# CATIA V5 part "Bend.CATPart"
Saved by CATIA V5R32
Part number: Bend
Bounding box of the stored display mesh (mm): x -50 to 50, y -150 to 15, z -50 to 115
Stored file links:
  D:\PROJECTS\Project 2022\CATIA V5 6R 2022\Resources\Part Files\c12_catia_v5_6r2022_prt\c12_catia_v5-6r2022 figr_12-44\Bend.CATPart
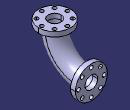
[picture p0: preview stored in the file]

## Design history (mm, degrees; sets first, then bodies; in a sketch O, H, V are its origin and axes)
Body1 (main body)
  Sketch1 on yz-plane, origin (0, 0, 0), H (0, 1, 0), V (0, 0, 1)
    arc A1 centre (0, 100) radius 100 from (-100, 100) to (0, 0) ccw
    point P1 (0, 100)
    coincidence: P1 V
  Sketch2 on zx-plane, origin (0, 0, 0), H (-1, 0, 0), V (0, 0, 1)
    circle A1 centre (0, 0) radius 30
    point P1 (0, -30)
    radius A1 = 30
    coincidence: A1 P1, P1 V
  Rib1: profile Sketch2, centre curve Sketch1
  Sketch3 on face of Rib1, origin (0, 0, 0), H (-1, 0, 0), V (0, 0, 1)
    circle A1 centre (0, 0) radius 50
    point P1 (0, -50)
    radius A1 = 50
    coincidence: A1 P1, P1 V
  Pad1: profile Sketch3, direction (0, 1, 0), length 15
  Sketch4 on face of Rib1, origin (0, 0, 100), H (1, 0, 0), V (0, 1, 0)
    circle A1 centre (0, -100) radius 50
    point P1 (0, -100)
    reference projected circle E1 centre (0, -100) radius 30 from edge [face of Rib1 | face of Rib1]
    radius A1 = 50
    coincidence: P1 V
    concentricity: A1 E1
  Pad2: profile Sketch4, direction (0, 0, 1), length 15
  Sketch5 on face of Pad1, origin (0, 15, 0), H (-1, 0, 0), V (0, 0, 1)
    circle A1 centre (0, 0) radius 20
    radius A1 = 20
  Sketch6 on yz-plane, origin (0, 0, 0), H (0, 1, 0), V (0, 0, 1)
    projected arc E1 centre (0, 100) radius 100 from (-100, 100) to (0, 0) ccw from edge of Sketch1
    line L1 (-100, 100) -> (-100, 115)
    point P3 (-100, 115)
    line L2 (0, 0) -> (15, 0)
    point P4 (15, 0)
    reference projected line E2 (15, 50) -> (15, -50) from edge [face of Pad1 | face of Pad1]
    reference projected line E3 (-50, 115) -> (-150, 115) from edge [face of Pad2 | face of Pad2]
    tangency: L1 E1, L2 E1
    coincidence: P4 E2, P3 E3
  Slot1: profile Sketch5, centre curve Sketch6
  Sketch7 on face of Pad1, origin (0, 15, 0), H (-1, 0, 0), V (0, 0, 1)
    circle A1 centre (0, -40) radius 6
    point P1 (0, -40)
    radius A1 = 6
    distance H P1 = 40
    coincidence: P1 V
  Pocket1: profile Sketch7, direction (0, -1, 0), length 15
  CircPattern1: of Pocket1, instances 8, angular step 45, axis from face of Pad1
  Sketch8 on face of Pad2, origin (0, 0, 115), H (1, 0, 0), V (0, 1, 0)
    circle A1 centre (0, -140) radius 6
    point P1 (0, -140)
    reference projected point E1 (0, -100) from vertex of Sketch1
    radius A1 = 6
    distance E1 P1 = 40
    coincidence: P1 V
  Pocket2: profile Sketch8, direction (0, 0, -1), length 15
  CircPattern2: of Pocket2, instances 8, angular step 45, axis from face of Pad2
